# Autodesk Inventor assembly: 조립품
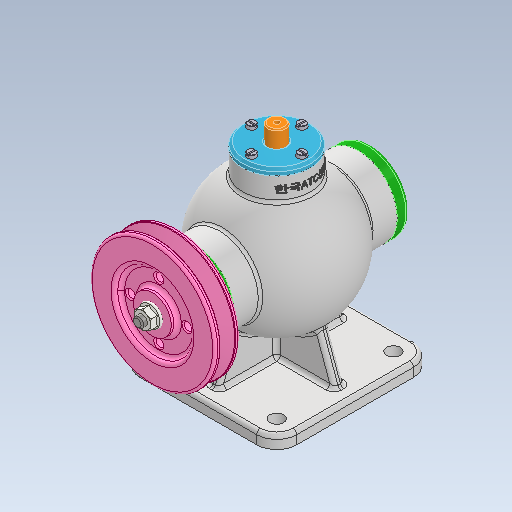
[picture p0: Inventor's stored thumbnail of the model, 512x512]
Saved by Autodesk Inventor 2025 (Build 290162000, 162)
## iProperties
Created: 2024-07
Part Number: 조립품
Document SubType Name: Assembly
Designer: 미서니
Author: 미서니
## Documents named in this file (15)
- C:\Users\미서니\OneDrive\바탕 화면\740708V1005\조립품.iam
- C:\Users\미서니\OneDrive\바탕 화면\740708V1005\본체.ipt
- C:\Users\미서니\OneDrive\바탕 화면\740708V1005\베어링- 6202\베어링- 6202.ipt
- C:\Users\미서니\OneDrive\바탕 화면\740708V1005\뒤커버\뒤커버.ipt
- C:\Users\미서니\OneDrive\바탕 화면\740708V1005\앞커버\앞커버.ipt
- C:\Users\미서니\OneDrive\바탕 화면\740708V1005\상부커버\상부커버.ipt
- C:\Users\미서니\OneDrive\바탕 화면\740708V1005\칼라\칼라.ipt
- C:\Users\미서니\OneDrive\바탕 화면\740708V1005\편심축\편심축.ipt
- C:\Users\미서니\OneDrive\바탕 화면\740708V1005\키 4 x 4 x 12\키 4 x 4 x 12.ipt
- C:\Users\미서니\OneDrive\바탕 화면\740708V1005\오일실 15 30 7\오일실 15 30 7.ipt
- C:\Users\미서니\OneDrive\바탕 화면\740708V1005\V-벨트풀리\V-벨트풀리.ipt
- C:\Users\미서니\OneDrive\바탕 화면\740708V1005\너트 M8\너트 M8.ipt
- C:\Users\미서니\OneDrive\바탕 화면\740708V1005\볼트 M4 x 16\볼트 M4 x 16.ipt
- C:\Users\미서니\OneDrive\바탕 화면\740708V1005\볼트 M4 x 12\볼트 M4 x 12.ipt
- C:\Users\미서니\OneDrive\바탕 화면\740708V1005\슬라이드\슬라이드.ipt
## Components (1 placed, 1 different names)
1. V-벨트풀리:1
